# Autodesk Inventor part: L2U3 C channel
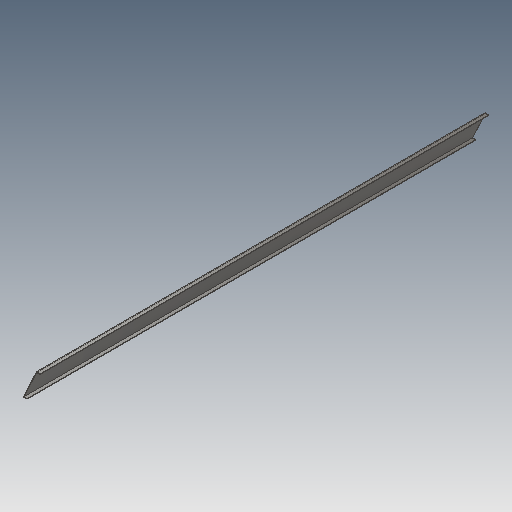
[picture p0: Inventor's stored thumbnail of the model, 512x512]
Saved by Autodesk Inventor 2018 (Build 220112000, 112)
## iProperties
Created: 2018-02
Part Number: L2U3 C channel
Material: Steel, Mild
Document SubType Name: Modeling
Designer: STK
Density: 7.85 g/cm^3
Appearance: Semi-Polished
Author: STK
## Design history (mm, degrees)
sketch "Sketch1"
  geometry: L1 (12.7, 177.8)-(12.7, -177.8); L2 (0, -190.5)-(0, 190.5); L3 (0, -190.5)-(92.075, -190.5); L4 (92.075, -190.5)-(92.075, -177.8); L5 (92.075, -177.8)-(12.7, -177.8); L6 (0, 190.5)-(92.075, 190.5); L7 (92.075, 190.5)-(92.075, 177.8); L8 (92.075, 177.8)-(12.7, 177.8); L9 (0, 0)-(92.075, 0)
  constraints: 18 end point, 3 horizontal, 3 parallel, 2 perpendicular, 2 vertical alignment, 1 collinear, 1 point on line, 1 vertical, 1 other
  dimensions: "d0" = 381 distance between parallel lines of L3 L6; "d1" = 12.7 distance between parallel lines of L6 L8; "d2" = 12.7 distance between parallel lines of L2 L1; "d3" = 92.075 distance of L2.end L6.end
extrude "Extrusion1" new body sketch "Sketch1" stored distance "d4" = 11430; taper "d5" = 0 deg
sketch "Sketch2"
  geometry: L1 (0, 0)-(-5134.804, 5915.55) reference; L2 (-11430, 381)-(0, 381) reference; L3 (0, 381)-(0, 0) reference; L4 (0, 381)-(-330.715, 381); L5 (-11430, 381)-(0, 381) reference; L6 (0, 0)-(-330.715, 381); L7 (0, 381)-(0, 0); L8 (0, 12.7)-(0, 368.3) reference; 1 further point
  constraints: 6 end point, 1 collinear, 1 point on line
extrude "Extrusion2" cut sketch "Sketch2" extent not by distance; stored distance "d6" = 11430; taper "d7" = 0 deg
sketch "Sketch3"
  geometry: L1 (5100.05, -5494.511)-(-34.754, 421.039) reference; L2 (0, 0)-(0, 381) reference; L3 (11430, 0)-(0, 0) reference; L4 (0, 381)-(0, 0); L5 (0, 0)-(330.715, 0); L6 (0, 381)-(11099.285, 381) reference; L7 (0, 381)-(330.715, 0); 1 further point
  constraints: 6 end point, 2 point on line, 1 vertical
extrude "Extrusion3" cut sketch "Sketch3" extent not by distance; stored distance "d8" = 11430; taper "d9" = 0 deg
body "Solid1"
node "Reference1"
node "Reference2"
